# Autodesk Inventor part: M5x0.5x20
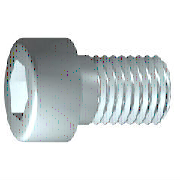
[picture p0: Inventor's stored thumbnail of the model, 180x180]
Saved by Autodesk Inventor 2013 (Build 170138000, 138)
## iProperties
IsCustomPart: 0
Company: 한국ATC센터
Created: 2014-07
Part Number: M5x0.5x20
Material: Steel, Mild
Description: 6각머리 태핑 나사
Document SubType Name: Modeling
Standard: KS B 1003
Designer: KYOUNG IL JANG
Standards Organization: KS
Language: ko-KR
Size Designation: M 5 x 20
Categories: <MemberInstance><Categories><Category DisplayName="조임쇠" InternalName="e4da775c-781d-43d5-af7c-5136215cf5a6" Mnemonic="FSTN"><Category DisplayName="볼트" InternalN
Density: 1 g/cm^3
Author: KYOUNG IL JANG
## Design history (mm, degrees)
sketch "스케치1"
  geometry: L1 (-1.167, 0)-(20, 0); L2 (20, 0)-(20, 2.5); L3 (20, 2.5)-(2, 2.5); L4 (2, 2.5)-(1.509, 2.5); L5 (1.509, 2.5)-(0, 2.5); L6 (0, 2.5)-(0, 4.25); L7 (0, 4.25)-(-5, 4.25); L8 (-5, 4.25)-(-5, 2.309); L9 (-5, 2.309)-(-2.5, 2.309); L10 (-2.5, 2.309)-(-1.167, 0); L11 (-10, 0)-(25, 0) reference; L12 (0, -0.85)-(0, 5.1) reference; L13 (2, 2.5)-(0, 2.5)
  constraints: 22 end point, 6 parallel, 2 collinear, 2 perpendicular, 1 horizontal, 1 point on line
  dimensions: "d1" = 18 distance from line of L3.end L2 (= GEL); "d2" = 0.49086 distance of L4.end L3.end (computed from GAL); "d3" = 5 distance between parallel lines of L8 L6 (= KOH); "d4" = 2.5 distance of L8.end L9.end (= INTI); "d5" = 60 deg angle of L10 L1; "d6" = 5 diameter of L3 L1 (= GD); "d7" = 5 diameter of L5 L1 (= BDM); "d8" = 4.6188 diameter of L9 L1 (= 1.1547 x SW); "d9" = 8.5 diameter of L7 L1 (= KOD); "d26" = 20 distance between parallel lines of L12 L2 (= NLG)
revolve "본체" sketch "스케치1" stored, may be unused: angle "d10" = 90 deg
sketch "스케치2"
  geometry: L1 (0, -5.95)-(0, 5.95) reference; L2 (-5.95, 0)-(5.95, 0) reference; L3 (2.309, 0)-(1.155, -2); L4 (1.155, -2)-(-1.155, -2); L5 (-1.155, -2)-(-2.309, 0); L6 (-2.309, 0)-(-1.155, 2); L7 (-1.155, 2)-(1.155, 2); L8 (1.155, 2)-(2.309, 0); 2 further points
  constraints: 12 end point, 1 coincident, 1 horizontal alignment, 1 point on line, 12 other
extrude "슬롯" join sketch "스케치2" stored distance "d11" = 10; taper "d12" = 0 deg
workplane "Work Plane1"
fillet "Fillet2" dims "d30" = 0.1 (= R)
body "Solid1"
fillet "모깎기1" dims "d17" = 0.5 (= RR)
feature "스레드" dims "d13" = 18 (= GEL), "d14" = 0
chamfer "모따기1" distance "d15" = 0.49076 (= -0.5 x SPD + 0.5 x GD); stored, may be unused: second distance "d16" = 0.49076 (= GUL), angle "d27" = 45 deg
other parameters: "GD" = 5 (= NND) [user parameter; used in 2 equation terms], "NLG" = 20 [user parameter; used in 1 equation term], "GEL" = 18 [user parameter; used in 2 equation terms], "KOD" = 8.5 [user parameter; used in 1 equation term], "KOH" = 5 [user parameter; used in 1 equation term], "INTI" = 2.5 [user parameter; used in 1 equation term], "GAL" = 0.49076 (= 0.61345 x PTC) [user parameter; used in 1 equation term], "GUL" = 0.49076 (= 0.61345 x PTC) [user parameter; used in 1 equation term], "BDM" = 5 (= NND) [user parameter; used in 1 equation term], "SW" = 4 [user parameter; used in 2 equation terms], "RR" = 0.5 [user parameter; used in 1 equation term], "SPD" = 4.01848 (= NND - 1.2269 x PTC) [user parameter; used in 1 equation term], "d19" = 0, "d28" = 0, "d29" = 0, "R" = 0.1 [user parameter; used in 1 equation term], "PHH" = 0.2 [user parameter], "GD1" = 4.01848 (= THREADDIA - 1.2269 x PTC) [user parameter], "THREADDIA" = 5 [user parameter; used in 1 equation term], "FAWI" = 45 deg [user parameter], "TPU" = 12.5 (computed from PTC) [user parameter], "PTC" = 0.8 [user parameter; used in 5 equation terms], "NND" = 5 [user parameter; used in 3 equation terms], "TOA" = 30 deg [user parameter], "E0" = 4.62 (= 1.155 x SW) [user parameter]
